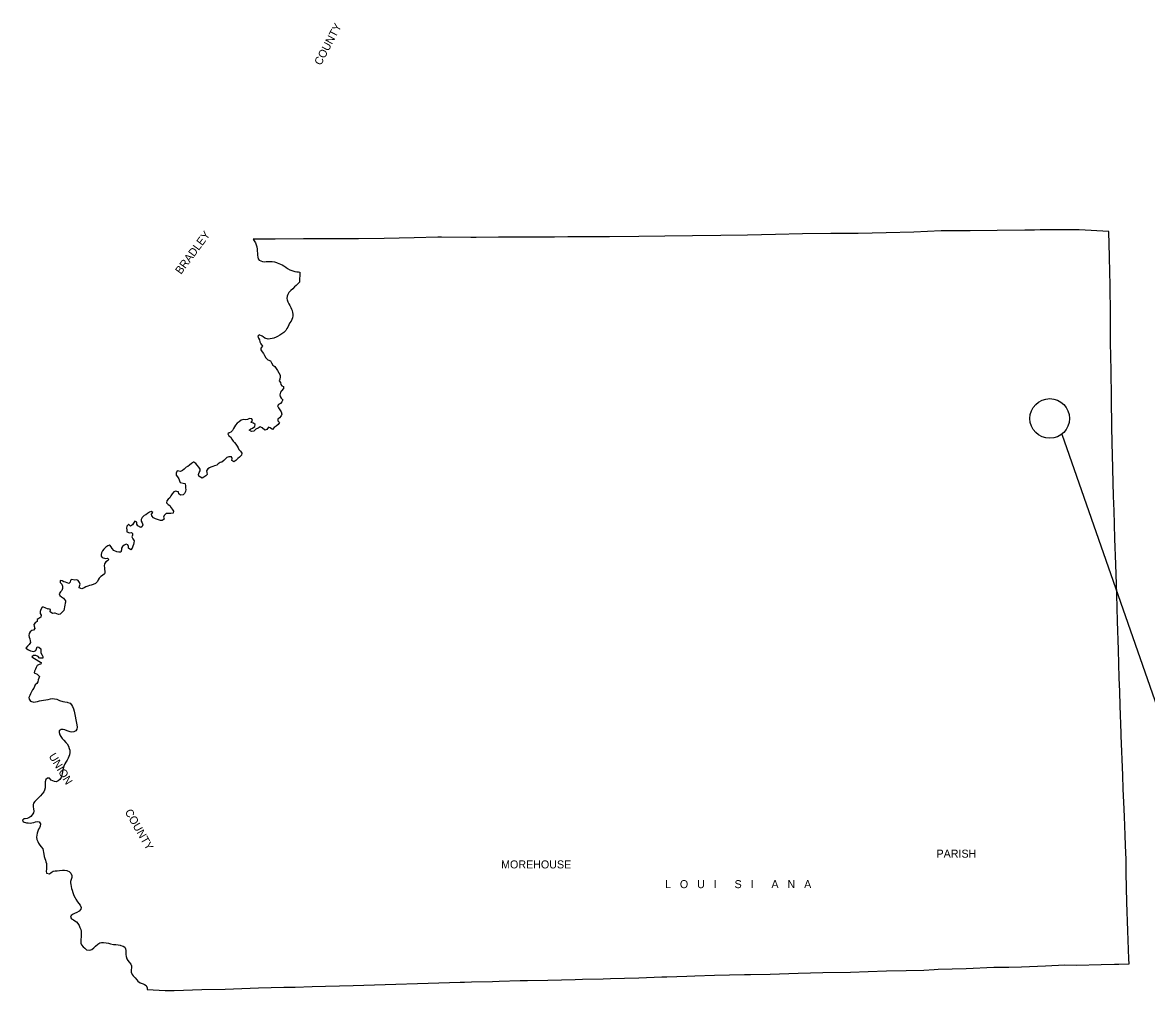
# Model space of a CAD drawing. Extents: x -2512 to 3792, y -435 to 2624.
# Drawn here: x 241 to 953, y 1301 to 1914 of the extents above; entities that cross this region are included whole.
import ezdxf

# ---------------------------------------------------------------- set-up
doc = ezdxf.new("R2010")
doc.units = 0
for name, color, linetype in [('2', 7, 'Continuous'), ('Level 30', 7, 'Continuous'), ('R_Annotation', 7, 'Continuous'), ('R_No Plot', 7, 'Continuous')]:
    doc.layers.add(name, color=color, linetype=linetype)

msp = doc.modelspace()

# ---------------------------------------------------------------- linework, layer by layer
at = {"layer": '2'}
msp.add_circle((891.26, 1663), 12.56, dxfattribs=at)
at = {"layer": 'R_Annotation'}
msp.add_line((898.98, 1653.09), (997.83, 1369.55), dxfattribs=at)
at = {"layer": 'R_No Plot'}
for p, q in [((416.2, 1755.62), (416.08, 1749.38)), ((392.36, 1715.07), (390.55, 1716.04)), ((316.39, 1594.64), (315.55, 1593.91)), ((303.89, 1581.96), (303.18, 1580.93)), ((267.82, 1547.49), (267.77, 1546.76)), ((271.58, 1346.25), (272.87, 1345.52)), ((935.03, 1317.49), (941.49, 1317.64))]:
    msp.add_line(p, q, dxfattribs=at)
for points in [[(885.31, 1782.36), (881.69, 1782.24), (875.45, 1782.22), (858, 1781.98), (840.84, 1781.86), (822.54, 1781.75), (805.1, 1780.86), (787.62, 1780.53), (769.85, 1780.12), (758.15, 1780.07)], [(910, 1782.5), (893.16, 1782.44), (885.31, 1782.36)], [(929.13, 1764.59), (929.1, 1765.74), (928.97, 1773.19), (928.75, 1781.41), (910, 1782.5)], [(469.62, 1776.92), (453.34, 1776.81), (435.81, 1776.66), (418.47, 1776.65), (400.61, 1776.5), (386.68, 1776.56)], [(386.68, 1776.56), (387.28, 1775.44), (388.09, 1774.11), (388.61, 1772.99), (388.95, 1771.67), (389.19, 1770.24), (389.27, 1769.02), (389.38, 1767.7), (389.4, 1766.39), (389.56, 1765.2), (389.8, 1764.15), (390.4, 1763.22), (392.52, 1762.46), (393.91, 1762.26), (394.98, 1762.28), (396.15, 1762.41), (397.42, 1762.42), (398.7, 1762.29), (400.11, 1762.14)], [(503.73, 1777.72), (488.56, 1777.33), (469.62, 1776.92)], [(527.97, 1777.62), (524.58, 1777.6), (506.05, 1777.76), (503.73, 1777.72)], [(630.9, 1778.32), (612.45, 1777.91), (594.86, 1778.1), (585.9, 1778.04), (577.62, 1777.83), (568.72, 1777.71), (559.61, 1777.7), (542.11, 1777.73), (527.97, 1777.62)], [(758.15, 1780.07), (752.5, 1780.05), (734.72, 1779.97), (717.58, 1779.55), (699.83, 1779.14), (682.81, 1778.84), (665.01, 1778.64), (647.47, 1778.51), (630.9, 1778.32)], [(400.11, 1762.14), (401.37, 1761.76), (401.77, 1761.59), (402.89, 1761.18), (404.02, 1760.69), (405.13, 1760.17), (406.12, 1759.66)], [(406.12, 1759.66), (407.32, 1758.77), (408.44, 1757.99), (409.78, 1757.19), (411.81, 1756.44), (413.03, 1756.15), (414.28, 1755.92), (415.38, 1755.79)], [(930.44, 1674.87), (930.44, 1675.98), (930.2, 1693.36), (929.86, 1711.13), (929.74, 1729.36), (929.61, 1746.77), (929.36, 1756.43), (929.13, 1764.59)], [(415.38, 1755.79), (416.2, 1755.62)], [(416.08, 1749.38), (414.88, 1748.24), (413.87, 1747.13), (412.9, 1746.28), (411.69, 1745.17), (410.43, 1743.99), (409.28, 1742.77), (408.55, 1741.57), (408.25, 1740.43), (408.06, 1739.06), (408.18, 1738.04), (408.61, 1736.88), (409.25, 1735.67), (409.79, 1734.6), (410.42, 1733.36), (410.93, 1732.26), (411.29, 1731.35), (411.63, 1730.13), (411.74, 1728.98), (411.74, 1727.88), (411.59, 1726.62), (411.25, 1725.57)], [(410.82, 1724.59), (409.71, 1723.26), (409.17, 1722.2), (408.53, 1720.86), (408.04, 1719.91), (407.26, 1718.72), (406.05, 1717.48)], [(411.25, 1725.57), (410.82, 1724.59)], [(406.05, 1717.48), (404.84, 1716.66), (403.47, 1715.72), (402.12, 1714.89)], [(390.55, 1716.04), (389.62, 1715.16)], [(389.62, 1715.16), (389.94, 1713.93), (390.64, 1712.75), (390.9, 1711.48), (391.59, 1710.21), (392.51, 1708.87), (391.52, 1707.6), (391.52, 1706.48), (392.35, 1705.24), (393.24, 1704.11), (393.9, 1702.86), (394.76, 1701.46), (395.91, 1700.15), (397.55, 1699.58), (398.25, 1698.15), (399.04, 1696.78)], [(393.05, 1714.76), (392.36, 1715.07)], [(401.19, 1714.41), (399.71, 1713.8), (398.64, 1713.56), (397.48, 1713.4), (396.08, 1713.12), (394.11, 1713.81), (393.05, 1714.76)], [(402.12, 1714.89), (401.19, 1714.41)], [(399.04, 1696.78), (400.28, 1695.81), (401.24, 1694.73), (402.04, 1693.38), (403, 1691.95), (403.7, 1690.34)], [(403.83, 1689.44), (403.48, 1687.97), (403.08, 1686.91), (404.01, 1685.78), (404.09, 1684.51), (404.72, 1683.69), (405.85, 1683.16), (405.81, 1681.94), (404.52, 1680.53), (404.07, 1679.63), (403.62, 1678.04), (403.72, 1676.99), (404.48, 1675.95), (405.49, 1674.7), (404.91, 1673.54), (403.95, 1672.51), (402.66, 1671.81), (402.04, 1671.03), (402.78, 1669.7), (403.56, 1668.41), (404.49, 1667.1), (404.72, 1665.63), (404.42, 1664.61), (403.25, 1663.48), (402.34, 1662.56), (402.19, 1661.41)], [(403.7, 1690.34), (403.83, 1689.44)], [(931.72, 1613.7), (931.38, 1622.47), (930.93, 1640.07), (930.83, 1647.32), (930.69, 1658.08), (930.44, 1674.87)], [(380.43, 1662.26), (379.13, 1662.02), (377.72, 1660.91), (376.62, 1659.94), (375.48, 1658.85), (374.88, 1657.65), (374.23, 1656.65), (373.62, 1655.39), (372.61, 1654.42), (371.42, 1653.96), (370.57, 1653.29), (371.24, 1651.93), (372.3, 1651.28)], [(383.15, 1662.36), (381.74, 1662.2), (380.43, 1662.26)], [(402.19, 1661.41), (403.36, 1660.52), (402.47, 1659.27), (401.16, 1658.03), (400.05, 1657.2), (399, 1655.98), (397.38, 1657.13), (396.44, 1657.43), (395.22, 1656.02), (394, 1655.66), (392.29, 1657), (391.1, 1657.74), (389.85, 1656.9), (388.39, 1656.18), (387.03, 1654.9), (385.66, 1654.75), (384.11, 1655.6), (385.25, 1656.37), (386.33, 1656.8), (387.66, 1657.96), (387.95, 1659.24), (386.85, 1659.93), (385.36, 1660.42), (386.32, 1661.64), (385.79, 1662.84), (384.36, 1662.95), (383.15, 1662.36)], [(372.3, 1651.28), (373.11, 1649.85), (374.05, 1648.64)], [(374.05, 1648.64), (374.92, 1647.71)], [(374.92, 1647.71), (375.64, 1646.62), (376.46, 1645.38)], [(376.46, 1645.38), (377.09, 1644.43)], [(377.09, 1644.43), (377.56, 1643.25), (378.55, 1642.21), (379.39, 1640.97), (379.29, 1639.75), (378.08, 1638.58), (376.96, 1637.55), (375.78, 1636.47), (374.47, 1635.46), (373.14, 1636.45), (373.38, 1637.58), (373.01, 1638.64), (372.75, 1638.8), (371.2, 1638.79), (369.91, 1638.32), (368.85, 1637.31)], [(352.5, 1628.69), (353.13, 1629.85), (353.11, 1630.86), (352.27, 1632.11), (351.1, 1633.39), (350.32, 1634.46), (349.14, 1635.27), (348.79, 1635.24), (347.54, 1634.54), (346.39, 1633.51), (345.24, 1632.5), (344.18, 1632.13), (342.98, 1630.88), (341.87, 1630.03)], [(357.97, 1631.12), (357.19, 1629.88), (357.23, 1628.8)], [(358.9, 1631.66), (357.97, 1631.12)], [(363.55, 1633.47), (362.24, 1633), (361.13, 1632.63), (359.91, 1632.13), (358.9, 1631.66)], [(364.49, 1634.27), (363.55, 1633.47)], [(368, 1636.38), (366.71, 1635.35), (365.78, 1635.09), (364.49, 1634.27)], [(368.85, 1637.31), (368, 1636.38)], [(341.87, 1630.03), (340.58, 1629.32), (338.54, 1629.81), (337.78, 1628.45), (337.93, 1627.18), (338.72, 1626.05), (339.6, 1624.79), (340.03, 1623.47), (340.43, 1622.37), (342.21, 1621.94), (343.35, 1621.84), (343.55, 1621.57), (343.85, 1620.38), (343.87, 1618.84)], [(357.23, 1628.8), (357.54, 1627.55), (356.62, 1626.62), (355.45, 1625.92), (354.31, 1625.28), (352.28, 1626.46), (352.08, 1627.59), (352.5, 1628.69)], [(339.03, 1616.59), (337.62, 1616.92), (336.44, 1616.44), (335.28, 1615.32), (334.5, 1614.08)], [(339.4, 1616.46), (339.03, 1616.59)], [(342.26, 1614.61), (340.58, 1614.34), (339.53, 1615.29), (339.4, 1616.46)], [(343.96, 1618.02), (343.8, 1616.73), (343.24, 1615.5)], [(343.87, 1618.84), (343.96, 1618.02)], [(334.5, 1614.08), (333.89, 1612.83), (332.74, 1611.97), (331.96, 1610.92), (331.77, 1609.62), (332.79, 1608.6), (333.89, 1607.87), (334.65, 1606.5), (335.28, 1605.54), (336.28, 1604.26), (336.04, 1603.07), (334.57, 1602.91), (333.46, 1602.89)], [(343.24, 1615.5), (342.26, 1614.61)], [(933.08, 1570.71), (932.53, 1586.72), (932.29, 1596.16), (931.98, 1604.53), (931.72, 1613.7)], [(322.24, 1602.42), (323.09, 1603.42), (322.02, 1604), (320.94, 1603.75), (319.78, 1602.72), (318.61, 1602.02), (317.6, 1601.53), (316.38, 1600.31), (315.8, 1599.03), (315.77, 1597.88)], [(327.9, 1598.29), (325.95, 1598.96), (324.76, 1599.52), (323.6, 1600.12), (322.48, 1601.3), (322.24, 1602.42)], [(332.57, 1602.91), (331.45, 1602.74), (330.33, 1601.62), (329.93, 1600.52), (330.27, 1599.31), (329.07, 1598.32), (327.9, 1598.29)], [(333.46, 1602.89), (332.57, 1602.91)], [(315.55, 1593.91), (313.54, 1594.95), (313, 1596.14), (312.92, 1597.33), (311.66, 1597.91), (310.76, 1596.71), (310.32, 1595.62), (309.03, 1594.73), (307.91, 1595.89), (307.75, 1595.92), (306.53, 1594.77)], [(315.77, 1597.88), (316.28, 1596.88)], [(316.28, 1596.88), (316.66, 1595.7), (316.39, 1594.64)], [(310.24, 1590.26), (310.13, 1589.1), (309.86, 1587.95), (310.41, 1586.68), (311.18, 1585.5), (311.13, 1584.21), (310.9, 1583.15), (310.44, 1582.05), (310.08, 1580.87), (309.26, 1579.85), (307.65, 1580.85), (307.71, 1581.92), (307.35, 1582.97), (306.21, 1583.37), (305.88, 1583.29), (304.88, 1582.82)], [(306.53, 1594.77), (306.36, 1593.61), (306.68, 1592.55), (306.69, 1591.31), (308.35, 1590.64), (309.5, 1590.72)], [(309.5, 1590.72), (310.24, 1590.26)], [(295.61, 1582.84), (294.49, 1582.32), (293.42, 1581.41), (292.15, 1580.34), (291.14, 1579.13), (290.6, 1577.94), (290.42, 1576.83), (290.28, 1575.8)], [(295.92, 1582.77), (295.61, 1582.84)], [(298.4, 1579.45), (297.25, 1580.7), (296.64, 1581.76), (295.92, 1582.77)], [(303.18, 1580.93), (303.18, 1579.77), (302.85, 1578.39)], [(304.88, 1582.82), (303.89, 1581.96)], [(290.28, 1575.8), (290.96, 1574.87)], [(290.96, 1574.87), (293.22, 1574.23), (294.33, 1574.48), (295.3, 1573.72)], [(295.3, 1573.72), (294.37, 1572.85)], [(302.85, 1578.39), (301.54, 1578.32), (300.33, 1578.57), (298.4, 1579.45)], [(294.37, 1572.85), (293.26, 1572.16), (292.48, 1571.02), (292.32, 1569.75), (292.39, 1568.48), (292.64, 1565.18)], [(936.55, 1461.98), (936.45, 1463.63), (935.8, 1481.1), (935.65, 1490.06), (935.34, 1498.83), (934.73, 1516.54), (934.18, 1534.63), (933.69, 1551.57), (933.08, 1570.71)], [(271.02, 1560.58), (270.81, 1559.38), (269.88, 1558.57), (267.78, 1559.25), (266.72, 1559.58), (265.66, 1560.22), (264.44, 1560.48), (264.35, 1559.12), (265.46, 1558.08), (265.9, 1556.88), (265.78, 1555.27), (265.52, 1554.11), (264.58, 1553.28), (263.66, 1552.03), (264.12, 1550.98), (265.24, 1549.96), (266.6, 1549.24), (267.82, 1547.49)], [(271.84, 1561), (271.02, 1560.58)], [(274.97, 1560.87), (273.75, 1560.69), (271.84, 1561)], [(275.89, 1560.42), (274.97, 1560.87)], [(292.64, 1565.18), (292.38, 1564.54), (291.24, 1563.55), (290.13, 1562.96), (289.04, 1561.92), (288.52, 1560.77), (288.03, 1559.73), (286.79, 1558.58), (285.27, 1557.83), (284.14, 1557.34), (283.04, 1557.23), (281.84, 1556.9), (280.59, 1556.4), (279.53, 1555.82), (278.22, 1555.09), (276.52, 1555.69), (276.59, 1556.74), (277.11, 1557.98), (276.55, 1559.09), (275.89, 1560.42)], [(267.6, 1545.96), (267.4, 1544.82), (267.16, 1543.66), (266.98, 1542.55), (266.62, 1541.46), (265.51, 1540.17), (264.45, 1539.18), (263.35, 1538.82), (261.29, 1539.63)], [(267.77, 1546.76), (267.6, 1545.96)], [(256.84, 1542.28), (254.96, 1543.04), (253.83, 1543.46), (253.03, 1543.45), (252.09, 1542.12), (251.68, 1540.73), (251.65, 1539.43), (252.39, 1538.39), (252.24, 1537.1), (250.86, 1536.25), (249.9, 1535.63), (249.76, 1534.44), (248.54, 1533.64), (247.65, 1532.56), (247.88, 1531.4), (248.3, 1530.07), (247.57, 1528.98), (246.38, 1528.81)], [(257.1, 1542.39), (256.84, 1542.28)], [(260.83, 1539.76), (259.64, 1539.41), (258.04, 1540.56), (258.17, 1541.98), (257.1, 1542.39)], [(261.29, 1539.63), (260.83, 1539.76)], [(246.38, 1528.81), (245.31, 1527.98), (244.83, 1526.81), (244.58, 1525.56), (244.76, 1524.59), (245.12, 1523.45), (245.41, 1522.29), (245.6, 1521.12), (244.68, 1519.86), (243.6, 1518.84), (242.65, 1517.65), (244.32, 1516.47), (245.54, 1515.86), (247.81, 1515.4), (249.02, 1516.07), (249.31, 1517.13), (249.8, 1518.38), (250.9, 1518.26), (252.17, 1517.05)], [(252.17, 1517.05), (252.07, 1516.07)], [(253.4, 1511.29), (251.31, 1511.21), (250.38, 1512.36), (248.92, 1512.89), (248.46, 1512.99), (247.43, 1512.97), (246.43, 1511.96), (248.05, 1510.91), (251.89, 1508.78)], [(252.07, 1516.07), (252.18, 1514.67), (253, 1513.18), (253.32, 1512.21)], [(253.32, 1512.21), (253.4, 1511.29)], [(252.44, 1508.56), (252.11, 1507.42), (250.99, 1507.25), (249.79, 1506.48), (249.28, 1505.26), (248.71, 1504.25), (248.09, 1503.02), (248, 1501.93), (249.82, 1501)], [(251.89, 1508.78), (252.44, 1508.56)], [(250.14, 1500.86), (251.24, 1499.71), (250.92, 1498.64), (250.45, 1497.45), (250.35, 1496.18), (249.65, 1495.21), (248.55, 1494.3), (248.1, 1493.22), (247.72, 1492.28), (246.9, 1491.19), (246.2, 1489.94), (245.57, 1488.59)], [(249.82, 1501), (250.14, 1500.86)], [(245.57, 1488.59), (245.19, 1487.61)], [(245.19, 1487.61), (244.64, 1486.4), (244.85, 1485.18), (245.52, 1483.91), (247.61, 1483.27), (248.67, 1483.49)], [(248.67, 1483.49), (249.94, 1483.83), (251.29, 1484.19), (252.62, 1484.44), (253.91, 1484.58), (255.35, 1484.8), (256.81, 1485.07)], [(256.81, 1485.07), (258.23, 1485.46), (259.36, 1485.62), (260.77, 1485.54), (262.22, 1485.17)], [(262.22, 1485.17), (262.64, 1485.01)], [(262.64, 1485.01), (264.07, 1484.36), (266.02, 1483.72), (267.37, 1483.6), (268.86, 1483.34), (269.35, 1483.16), (270.64, 1482.63), (271.6, 1481.69), (272.14, 1480.61), (272.75, 1479.07), (273.16, 1477.64), (275.03, 1468.91)], [(275.03, 1468.91), (275.07, 1467.54), (274.89, 1466.26)], [(274.42, 1465.28), (273.07, 1464.52), (271.84, 1464.46), (270.72, 1464.63), (268.81, 1465.3), (267.26, 1465.82), (266.4, 1466.04), (265.04, 1466.13), (263.82, 1465.29), (263.68, 1464.05), (264.14, 1462.68), (264.76, 1461.66), (265.73, 1460.34), (266.73, 1459.21), (267.91, 1457.92), (268.78, 1456.9), (269.61, 1455.5), (270.18, 1454.11), (270.43, 1452.86), (270.48, 1451.46), (270.28, 1450.02), (269.95, 1448.9), (269.53, 1447.85), (268.77, 1446.61), (268.01, 1445.45), (267.31, 1444.22), (266.8, 1442.92), (266.3, 1441.41)], [(274.89, 1466.26), (274.42, 1465.28)], [(941.49, 1317.64), (941.4, 1320.91), (940.81, 1338.61), (940.17, 1356.72), (939.59, 1375.12), (939.58, 1383.73), (939.35, 1392.64), (939.1, 1399.05), (938.55, 1410.89), (938.27, 1420), (937.83, 1428.34), (937.48, 1437.21), (936.55, 1461.98)], [(266.3, 1441.41), (266.07, 1440.73), (265.93, 1439.45), (265.75, 1438.03), (265.51, 1437.04), (265.02, 1435.76), (264.2, 1434.47), (263.18, 1433.55), (261.87, 1432.97), (260.84, 1433.02), (258.66, 1433.96)], [(258.66, 1433.96), (257.63, 1435.24), (256.43, 1435.31), (255.3, 1434.3), (254.82, 1432.82), (254.8, 1431.69), (254.94, 1430.46), (254.97, 1429.06), (254.53, 1427.6), (254.04, 1426.64), (253.09, 1425.23), (251.97, 1423.96), (250.75, 1422.79), (249.52, 1421.7), (248.36, 1420.48), (247.6, 1419.39)], [(247.27, 1418.41), (247.26, 1417.08), (247.5, 1415.74), (247.61, 1414.33), (247.4, 1413.18), (246.74, 1412.02), (245.84, 1410.97), (244.65, 1410.05), (243.42, 1409.74), (242.31, 1409.56), (241.35, 1409.52), (240.52, 1408.66), (240.86, 1407.53), (243.17, 1406.91), (244.23, 1406.85), (245.3, 1406.81), (246.41, 1406.96), (247.74, 1407.18), (248.81, 1407.53), (249.96, 1407.72), (251.17, 1407.48), (251.96, 1406.3), (251.73, 1404.91)], [(247.6, 1419.39), (247.27, 1418.41)], [(251.73, 1404.91), (251.29, 1403.89), (250.68, 1402.88), (250.22, 1401.72), (249.79, 1400.43), (249.53, 1399.12), (249.41, 1397.8), (249.62, 1396.44), (250.16, 1395.06), (250.65, 1394.05), (251.53, 1392.82), (252.33, 1391.77), (253.32, 1390.4)], [(253.32, 1390.4), (253.69, 1389.46)], [(253.69, 1389.46), (253.83, 1388.25), (254, 1387.06), (254.35, 1385.67), (254.78, 1384.45), (255.14, 1383.34), (255.4, 1382.35), (255.73, 1381.21), (255.78, 1379.88), (255.77, 1378.93), (255.75, 1377.64), (255.63, 1376.25), (255.77, 1375)], [(255.77, 1375), (257.73, 1374.59), (258.79, 1375.53), (259.89, 1376.25)], [(259.89, 1376.25), (261.21, 1376.53), (262.52, 1376.62), (264.07, 1376.7), (265.87, 1376.91), (267.12, 1377), (268.54, 1376.8)], [(268.54, 1376.8), (269.07, 1376.62)], [(269.07, 1376.62), (270.07, 1376.06), (271.19, 1375.1), (271.82, 1373.56), (271.69, 1372.4), (271.16, 1370.51), (271.04, 1369.85), (270.97, 1368.87), (271.05, 1367.94), (271.3, 1366.61), (271.67, 1365.45), (272.03, 1364.31), (272.44, 1362.78), (272.66, 1362.12), (273.08, 1361), (273.9, 1359.48)], [(274.42, 1358.54), (275.4, 1356.93), (276.19, 1355.87), (277.02, 1354.79), (277.63, 1353.38), (277.4, 1352.2), (276.42, 1350.93), (275.01, 1350.21), (273.56, 1349.6)], [(273.9, 1359.48), (274.42, 1358.54)], [(272.65, 1349.21), (271.4, 1348.33), (270.92, 1347.21)], [(270.92, 1347.21), (271.58, 1346.25)], [(273.56, 1349.6), (272.65, 1349.21)], [(272.87, 1345.52), (273.73, 1344.96)], [(273.73, 1344.96), (274.81, 1344.16), (275.64, 1343.15), (276.39, 1341.94), (276.91, 1340.76), (277.41, 1339.35), (277.61, 1338.31), (277.71, 1337.09)], [(277.71, 1337.09), (277.67, 1335.83), (277.63, 1334.52), (277.49, 1333.25), (277.39, 1331.91), (277.53, 1330.77), (277.99, 1329.68), (278.99, 1328.37), (279.95, 1327.52), (281.11, 1326.58), (283.23, 1326.28), (284.36, 1326.75), (285.67, 1327.84), (286.75, 1328.79), (288.25, 1330.21), (289.45, 1330.97), (290.55, 1331.28), (291.95, 1331.25), (293.62, 1331.04), (295.03, 1330.76), (296.27, 1330.43), (298.18, 1329.96), (299.72, 1329.91), (301.24, 1329.79), (302.39, 1329.53), (302.8, 1329.36), (304.27, 1328.81), (305.31, 1328.24), (305.86, 1327.13)], [(305.86, 1327.13), (306.06, 1326.16)], [(306.06, 1326.16), (306.06, 1324.89), (306.08, 1323.67), (306.18, 1322.23), (306.57, 1320.86)], [(306.57, 1320.86), (307.23, 1319.84), (308.09, 1318.8), (309.16, 1317.49), (309.5, 1316.3), (309.56, 1315.08), (309.4, 1313.83), (309.37, 1312.36), (309.91, 1311.01)], [(900.84, 1316.97), (908.47, 1316.81), (923.95, 1317.22), (932.33, 1317.43), (935.03, 1317.49)], [(309.91, 1311.01), (310.61, 1310.05)], [(645.53, 1309.41), (648.73, 1309.5), (661.36, 1309.89), (666.35, 1309.97), (678.98, 1310.4), (697.91, 1310.89), (701.61, 1310.93), (714.19, 1311.2), (731.82, 1311.71), (747.48, 1312.13), (765.13, 1312.45), (776.22, 1312.84)], [(776.22, 1312.84), (787.85, 1313.16), (800.22, 1313.48), (811.57, 1313.66), (817.99, 1314.11), (820.6, 1314.29), (838.35, 1314.64), (855.88, 1315.49), (865.28, 1315.63), (873.37, 1315.86), (888.66, 1316.49), (900.84, 1316.97)], [(310.61, 1310.05), (311.85, 1308.83), (312.92, 1307.58)], [(312.92, 1307.58), (313.64, 1306.64)], [(313.64, 1306.64), (315.04, 1305.69), (316.91, 1304.92), (317.77, 1304.49), (318.98, 1303.87), (319.5, 1302.44), (319.59, 1301.49)], [(390.1, 1302.45), (406.1, 1302.9), (413.2, 1303), (423.96, 1303.31), (432.39, 1303.48), (441.33, 1303.7), (450.01, 1304.02), (517.77, 1306.02)], [(517.77, 1306.02), (520.45, 1306.09), (524.94, 1306.23), (538.33, 1306.55)], [(538.33, 1306.55), (542.54, 1306.66), (555.79, 1307.02), (560.34, 1307.1), (573.31, 1307.42), (590.74, 1307.85), (595.3, 1307.94), (608.3, 1308.22), (613.11, 1308.38), (621.86, 1308.6), (630.92, 1308.76), (645.53, 1309.41)], [(319.59, 1301.49), (330.9, 1300.78), (336.67, 1300.84), (354.23, 1301.32), (368.91, 1301.68), (390.1, 1302.45)]]:
    msp.add_lwpolyline(points, dxfattribs=at)

# ---------------------------------------------------------------- texts
at = {"layer": 'Level 30'}
for s, rotation, p in [('COUNTY', 62.24146, (429.54, 1886.17)), ('BRADLEY', 53.44753, (340.9, 1753.85)), ('UNION', 301.30412, (256.94, 1449.2)), ('COUNTY', 299.67849, (305.15, 1413.93))]:
    msp.add_text(s, height=5.069, rotation=rotation, dxfattribs=at).set_placement(p)
for s, height, p in [('PARISH', 5.069, (819.54, 1384.89)), ('MOREHOUSE', 5.069, (543.71, 1378.09)), ('L   O   U   I      S   I      A   N   A', 5.0688, (647.54, 1365.6))]:
    msp.add_text(s, height=height, dxfattribs=at).set_placement(p)

doc.saveas('drawing.dxf')
